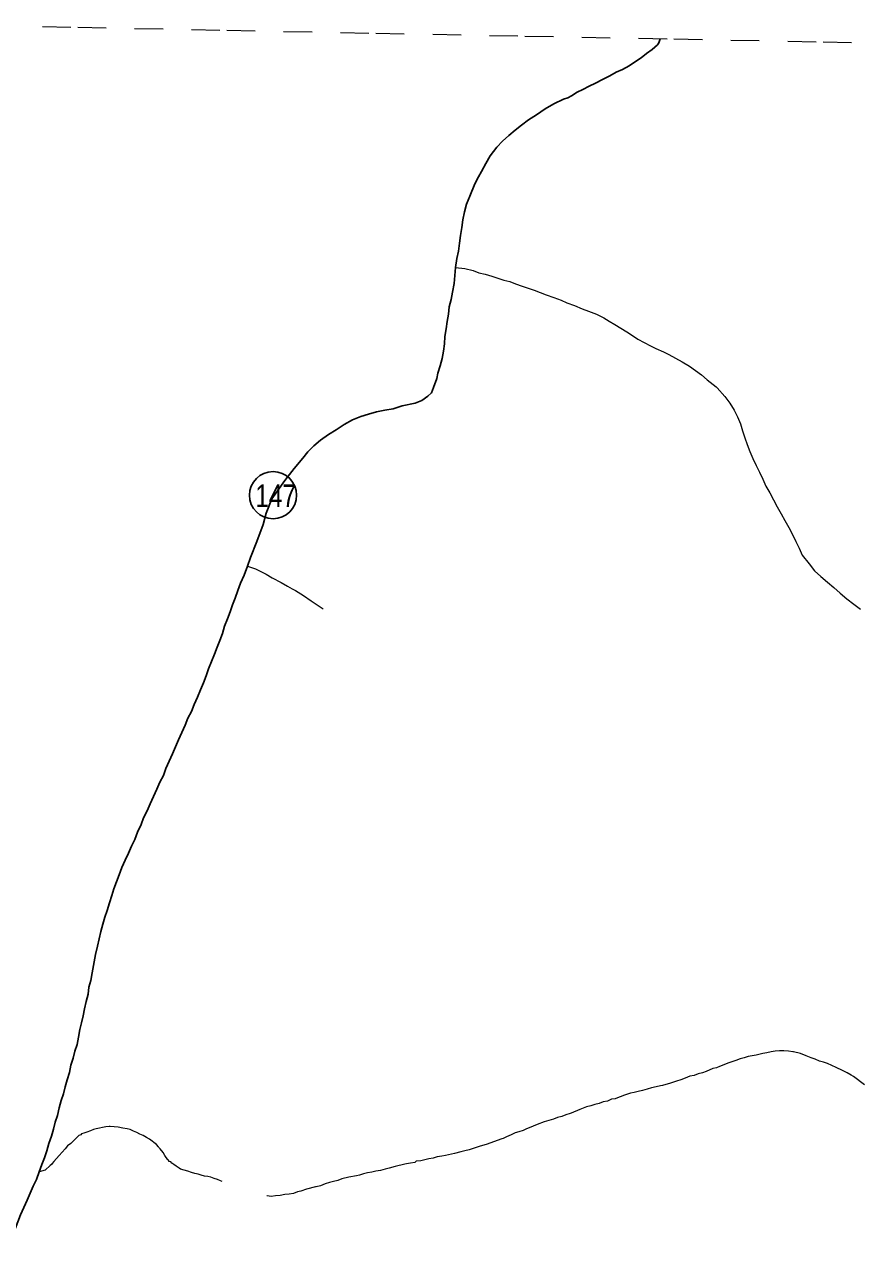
# Model space of a CAD drawing. Extents: x 781.9 to 808.1, y 7453.3 to 7481.5.
# Drawn here: x 796.397 to 799.324, y 7476.942 to 7481.24 of the extents above; entities that cross this region are included whole.
import ezdxf
from ezdxf.enums import TextEntityAlignment as Align

# ---------------------------------------------------------------- set-up
doc = ezdxf.new("R2010")
doc.units = 0
doc.header["$LTSCALE"] = 0.032
for name, pattern in [('LONG_DASHED', [7.5, 6, -1.5]), ('MEDIUM_DASHED', [4.5, 3, -1.5]), ('SHORT_DASHED', [2.7, 1.5, -1.2])]:
    doc.linetypes.add(name, pattern=pattern)
for name, color, linetype, lineweight in [('13', 7, 'Continuous', 25), ('35', 7, 'SHORT_DASHED', 13), ('4', 7, 'LONG_DASHED', 25), ('5', 7, 'LONG_DASHED', 13), ('6', 7, 'MEDIUM_DASHED', 13)]:
    doc.layers.add(name, color=color, linetype=linetype, lineweight=lineweight)
doc.layers.add('61', color=7, linetype='Continuous')

msp = doc.modelspace()

# ---------------------------------------------------------------- linework, layer by layer
at = {"layer": '13'}
msp.add_circle((797.2716, 7479.583), 0.083, dxfattribs=at)
msp.add_circle((797.2716, 7479.583), 0.083, dxfattribs=at)
msp.add_circle((797.2716, 7479.583), 0.083, dxfattribs=at)
at = {"layer": '35'}
msp.add_lwpolyline([(796.0603, 7481.2401), (796.5846, 7481.2299), (797.1089, 7481.2197), (797.6332, 7481.2094), (798.1576, 7481.1991), (798.6819, 7481.1889), (799.2062, 7481.1785), (799.7305, 7481.1682), (800.2549, 7481.1579), (800.7792, 7481.1475), (801.3035, 7481.1371), (801.8278, 7481.1267), (802.3522, 7481.1163), (802.8765, 7481.1059), (803.4008, 7481.0954), (803.9252, 7481.0849), (804.4495, 7481.0745), (804.9739, 7481.0639), (805.4982, 7481.0534), (806.0225, 7481.0429), (806.5469, 7481.0323), (807.0712, 7481.0217), (807.5956, 7481.0111), (808.1199, 7481.0005)], dxfattribs=at)
at = {"layer": '4'}
for points in [[(798.6337, 7481.1898), (798.6313, 7481.1823), (798.6282, 7481.175), (798.6236, 7481.1677), (798.6057, 7481.1515), (798.5854, 7481.1378), (798.5668, 7481.1223), (798.5466, 7481.1101), (798.5238, 7481.0947), (798.5012, 7481.0817), (798.4784, 7481.072), (798.4557, 7481.059), (798.4306, 7481.0461), (798.4055, 7481.0331), (798.3835, 7481.0226), (798.3617, 7481.0112), (798.3414, 7481.0015), (798.3212, 7480.9893), (798.3082, 7480.982), (798.2932, 7480.9769), (798.2595, 7480.9601), (798.2287, 7480.9431), (798.1979, 7480.922), (798.1704, 7480.9042), (798.146, 7480.8856), (798.1233, 7480.8677), (798.1006, 7480.8491), (798.0787, 7480.8288), (798.0593, 7480.8078), (798.0357, 7480.7777), (798.0203, 7480.7502), (798.0049, 7480.7226), (797.9944, 7480.704), (797.9814, 7480.6788), (797.9636, 7480.6351), (797.9522, 7480.6075), (797.9449, 7480.5799), (797.9393, 7480.5524), (797.9352, 7480.5248), (797.9304, 7480.4972), (797.9271, 7480.4697), (797.9239, 7480.4421), (797.9183, 7480.4157), (797.9135, 7480.3845)], [(797.9135, 7480.3845), (797.9087, 7480.3277), (797.9028, 7480.2978), (797.8979, 7480.2718), (797.8914, 7480.2459), (797.8882, 7480.2199), (797.8841, 7480.194), (797.8801, 7480.1681), (797.876, 7480.1421), (797.8752, 7480.1161), (797.8712, 7480.0902), (797.8663, 7480.0643), (797.859, 7480.0383), (797.8517, 7480.0124), (797.8477, 7479.9937), (797.8363, 7479.9621), (797.829, 7479.9434), (797.816, 7479.9313), (797.7952, 7479.9169), (797.772, 7479.9073), (797.7256, 7479.8977), (797.6936, 7479.8875), (797.6644, 7479.8827), (797.6353, 7479.877), (797.6077, 7479.8681), (797.5801, 7479.86), (797.5509, 7479.8478), (797.5217, 7479.8316), (797.4942, 7479.8129), (797.4666, 7479.7967), (797.4391, 7479.7772), (797.4147, 7479.757), (797.3944, 7479.7351), (797.3758, 7479.7132), (797.3454, 7479.6772), (797.3126, 7479.6348), (797.267, 7479.57), (797.247, 7479.5196), (797.2366, 7479.4796), (797.2142, 7479.4204), (797.1918, 7479.3636), (797.1822, 7479.3332)], [(797.1822, 7479.3332), (797.1702, 7479.3012), (797.1577, 7479.273), (797.148, 7479.247), (797.1382, 7479.2211), (797.1293, 7479.1968), (797.1204, 7479.1724), (797.1115, 7479.1481), (797.1009, 7479.1222), (797.0937, 7479.0962), (797.0839, 7479.0719), (797.075, 7479.0476)], [(797.075, 7479.0476), (797.0661, 7479.0233), (797.0555, 7478.9973), (797.045, 7478.9714), (797.0369, 7478.947), (797.0272, 7478.9227), (797.0166, 7478.8984)], [(797.0166, 7478.8984), (797.0061, 7478.8725), (796.9947, 7478.8465), (796.9842, 7478.8222), (796.972, 7478.7979), (796.9623, 7478.7735), (796.9509, 7478.7476), (796.9396, 7478.7217), (796.9289, 7478.6973), (796.9185, 7478.673), (796.9063, 7478.6471), (796.8942, 7478.6211), (796.8861, 7478.5968), (796.8739, 7478.5725), (796.8626, 7478.5481), (796.8512, 7478.5222), (796.8399, 7478.4963), (796.8285, 7478.4719), (796.8164, 7478.4476), (796.8074, 7478.4233), (796.7953, 7478.3973), (796.7855, 7478.3714), (796.7734, 7478.3471), (796.7627, 7478.3228), (796.7515, 7478.2984), (796.7401, 7478.2725), (796.7304, 7478.2465), (796.7207, 7478.2222), (796.7118, 7478.1979), (796.7045, 7478.1737), (796.6964, 7478.1476), (796.6883, 7478.1217), (796.6801, 7478.0974), (796.6729, 7478.073), (796.6664, 7478.0471), (796.6599, 7478.0212), (796.6542, 7477.996), (796.6469, 7477.966), (796.6396, 7477.9271), (796.6356, 7477.9012), (796.6307, 7477.8752), (796.6242, 7477.8509), (796.621, 7477.8266), (796.6145, 7477.8006), (796.6088, 7477.7747), (796.604, 7477.7504), (796.5983, 7477.726), (796.5918, 7477.7017), (796.5877, 7477.6758), (796.5821, 7477.6498), (796.5748, 7477.6255), (796.5691, 7477.6012), (796.5602, 7477.5769), (796.5553, 7477.5509), (796.5472, 7477.525), (796.5407, 7477.5006), (796.5342, 7477.4763), (796.5261, 7477.452), (796.5196, 7477.4261), (796.5131, 7477.4001), (796.5058, 7477.3758), (796.4994, 7477.3515), (796.4921, 7477.3271), (796.4831, 7477.3012), (796.4758, 7477.2752), (796.4677, 7477.2509), (796.4588, 7477.2266), (796.4491, 7477.2007)], [(796.4491, 7477.2007), (796.4394, 7477.1747), (796.428, 7477.1504), (796.4175, 7477.1261), (796.4069, 7477.1017), (796.3948, 7477.0758), (796.3833, 7477.0499), (796.3737, 7477.0255), (796.364, 7477.0012), (796.351, 7476.9769), (796.3503, 7476.9745), (796.3415, 7476.9561), (796.3319, 7476.9417)]]:
    msp.add_lwpolyline(points, dxfattribs=at)
at = {"layer": '5'}
for points in [[(797.9135, 7480.3845), (797.9466, 7480.3804), (797.975, 7480.374), (797.9952, 7480.3659), (798.0179, 7480.361), (798.0406, 7480.3545), (798.0617, 7480.3472), (798.0828, 7480.3399), (798.1039, 7480.335), (798.125, 7480.3269), (798.1477, 7480.3188), (798.1687, 7480.3115), (798.1898, 7480.3043), (798.2109, 7480.2969), (798.232, 7480.288), (798.2595, 7480.2791), (798.2847, 7480.2694), (798.3049, 7480.2605), (798.3325, 7480.2507), (798.3593, 7480.2394), (798.3812, 7480.2305), (798.4095, 7480.2199), (798.4346, 7480.2078), (798.4541, 7480.1956), (798.4735, 7480.1842), (798.4947, 7480.1713), (798.5158, 7480.1583), (798.536, 7480.1453), (798.5546, 7480.1324), (798.5765, 7480.1202), (798.5992, 7480.1088), (798.6179, 7480.0991), (798.6446, 7480.0878), (798.6633, 7480.078), (798.6876, 7480.0659), (798.7111, 7480.0521), (798.7362, 7480.0375), (798.7792, 7480.0063), (798.7984, 7479.9895), (798.8304, 7479.9639), (798.8336, 7479.9605), (798.8603, 7479.9305), (798.8781, 7479.9069), (798.8935, 7479.8827), (798.9049, 7479.8583), (798.9154, 7479.834), (798.9227, 7479.8097), (798.9316, 7479.7854), (798.9398, 7479.761), (798.9487, 7479.7367), (798.9592, 7479.7124), (798.9706, 7479.6881), (798.9827, 7479.6638), (798.9941, 7479.6394), (799.0054, 7479.6151), (799.0192, 7479.5908), (799.0322, 7479.5665), (799.0444, 7479.5421), (799.0588, 7479.5178), (799.0719, 7479.4935), (799.0857, 7479.4692), (799.0987, 7479.4449), (799.11, 7479.4205), (799.1222, 7479.3962), (799.1327, 7479.3719), (799.157, 7479.341), (799.1765, 7479.3167), (799.1984, 7479.2965), (799.2219, 7479.277), (799.2438, 7479.2584), (799.2665, 7479.2381), (799.29, 7479.2178), (799.3143, 7479.1992), (799.3378, 7479.1814)], [(797.1822, 7479.3332), (797.2093, 7479.3238), (797.2469, 7479.3046), (797.2688, 7479.2916), (797.2996, 7479.2754), (797.3223, 7479.2624), (797.3385, 7479.2535), (797.3511, 7479.2478), (797.3782, 7479.23), (797.4058, 7479.2113), (797.4479, 7479.1831)]]:
    msp.add_lwpolyline(points, dxfattribs=at)
at = {"layer": '6'}
for points in [[(799.3518, 7477.5077), (799.3129, 7477.537), (799.3054, 7477.542), (799.2908, 7477.5493), (799.2746, 7477.5574), (799.2519, 7477.5687), (799.2219, 7477.5825), (799.2081, 7477.5874), (799.1935, 7477.5914), (799.179, 7477.5979), (799.1644, 7477.6028), (799.1465, 7477.6092), (799.1271, 7477.6174), (799.1019, 7477.6239), (799.0995, 7477.6238), (799.0849, 7477.6263), (799.0687, 7477.6271), (799.0525, 7477.6271), (799.0379, 7477.6263), (799.0233, 7477.6238), (799.0087, 7477.6206), (798.9941, 7477.6182), (798.9714, 7477.6117), (798.943, 7477.6077), (798.9292, 7477.6028), (798.9146, 7477.5987), (798.9, 7477.593), (798.8855, 7477.589), (798.8709, 7477.5841), (798.8571, 7477.5784), (798.8417, 7477.572), (798.8319, 7477.5671), (798.8181, 7477.5646), (798.7954, 7477.5542), (798.7817, 7477.5493), (798.7671, 7477.546), (798.7525, 7477.5403), (798.7379, 7477.5379), (798.7217, 7477.5306), (798.7055, 7477.525), (798.6908, 7477.5201), (798.6698, 7477.5136), (798.6414, 7477.5055), (798.6341, 7477.5038), (798.6195, 7477.5006), (798.6033, 7477.4965), (798.5871, 7477.4925), (798.5709, 7477.4876), (798.5563, 7477.4844), (798.5417, 7477.4811), (798.5287, 7477.4779), (798.5076, 7477.4706), (798.4776, 7477.4593), (798.4752, 7477.4584), (798.4622, 7477.4568), (798.4476, 7477.4503), (798.433, 7477.4471), (798.4185, 7477.4422), (798.4039, 7477.4382), (798.3893, 7477.4341), (798.3747, 7477.4301), (798.3504, 7477.4212), (798.3203, 7477.4082), (798.3163, 7477.4066), (798.3017, 7477.4017), (798.2871, 7477.396), (798.2725, 7477.392), (798.2579, 7477.3871), (798.2417, 7477.3822), (798.2255, 7477.3774), (798.2012, 7477.3684), (798.1728, 7477.3563), (798.163, 7477.3522), (798.1509, 7477.3466), (798.1363, 7477.3417)], [(797.0928, 7477.1674), (797.0872, 7477.1698), (797.0758, 7477.1747), (797.0645, 7477.1779), (797.0531, 7477.182), (797.0418, 7477.1844), (797.0304, 7477.186), (797.0191, 7477.1893), (797.0077, 7477.1925), (796.9964, 7477.1958), (796.985, 7477.199), (796.9721, 7477.2039), (796.9461, 7477.2112), (796.9412, 7477.2144), (796.9308, 7477.2209), (796.9226, 7477.2266), (796.9153, 7477.2322), (796.912, 7477.2363), (796.9055, 7477.2379), (796.9047, 7477.242), (796.9015, 7477.2437), (796.8909, 7477.2582), (796.8853, 7477.2688), (796.8747, 7477.2825), (796.8699, 7477.2874), (796.8691, 7477.289), (796.8617, 7477.2971), (796.8366, 7477.3166), (796.8261, 7477.3222), (796.8148, 7477.3287), (796.8034, 7477.3336), (796.7921, 7477.3393), (796.7807, 7477.3441), (796.7694, 7477.3498), (796.758, 7477.353), (796.7434, 7477.3547), (796.7272, 7477.3587), (796.6988, 7477.3612), (796.6948, 7477.3603), (796.6834, 7477.3595), (796.6721, 7477.3571), (796.6607, 7477.3555), (796.6494, 7477.353), (796.6396, 7477.3498), (796.6299, 7477.3457), (796.6169, 7477.3409), (796.6056, 7477.3368), (796.5974, 7477.3352), (796.5958, 7477.332), (796.5885, 7477.3287), (796.5626, 7477.3036), (796.5602, 7477.3012), (796.5488, 7477.2931), (796.5399, 7477.2818), (796.5293, 7477.2704), (796.5196, 7477.259), (796.5099, 7477.2477), (796.501, 7477.2371), (796.4945, 7477.2306), (796.4928, 7477.2274), (796.4921, 7477.2274), (796.488, 7477.2233), (796.4699, 7477.2069), (796.4491, 7477.2007)], [(798.1363, 7477.3417), (798.1233, 7477.3385), (798.1087, 7477.332), (798.0925, 7477.3247), (798.0812, 7477.319), (798.076, 7477.3179), (798.0218, 7477.2974)], [(798.0218, 7477.2974), (798.0001, 7477.2917), (797.9612, 7477.2785), (797.9466, 7477.2752), (797.932, 7477.272), (797.9093, 7477.2663), (797.8777, 7477.259), (797.8655, 7477.2566), (797.8493, 7477.2541), (797.8347, 7477.2493), (797.8201, 7477.2476), (797.8055, 7477.2436), (797.7909, 7477.2395), (797.7755, 7477.2387), (797.773, 7477.2363), (797.7698, 7477.2339), (797.7552, 7477.2322), (797.7407, 7477.229), (797.735, 7477.2282), (797.7017, 7477.2201), (797.6798, 7477.2136), (797.6661, 7477.2104), (797.6499, 7477.2062), (797.6336, 7477.2039), (797.619, 7477.2006), (797.6044, 7477.1974), (797.5899, 7477.1941), (797.5753, 7477.1901), (797.5647, 7477.1877), (797.538, 7477.182), (797.5136, 7477.1763), (797.499, 7477.1706), (797.4845, 7477.1674), (797.4699, 7477.1633), (797.4553, 7477.1585), (797.4391, 7477.152), (797.4228, 7477.1487), (797.4204, 7477.1479), (797.3888, 7477.1406), (797.3693, 7477.1333), (797.358, 7477.1309), (797.3434, 7477.1252), (797.3288, 7477.1228), (797.3126, 7477.1212), (797.2964, 7477.1179), (797.2801, 7477.1163), (797.2655, 7477.1147), (797.251, 7477.1171), (797.2501, 7477.1171)]]:
    msp.add_lwpolyline(points, dxfattribs=at)

# ---------------------------------------------------------------- texts
at = {"layer": '61', "width": 0.8}
msp.add_text('147', height=0.08, dxfattribs=at).set_placement((797.2808, 7479.541), align=Align.CENTER)

doc.saveas('drawing.dxf')
